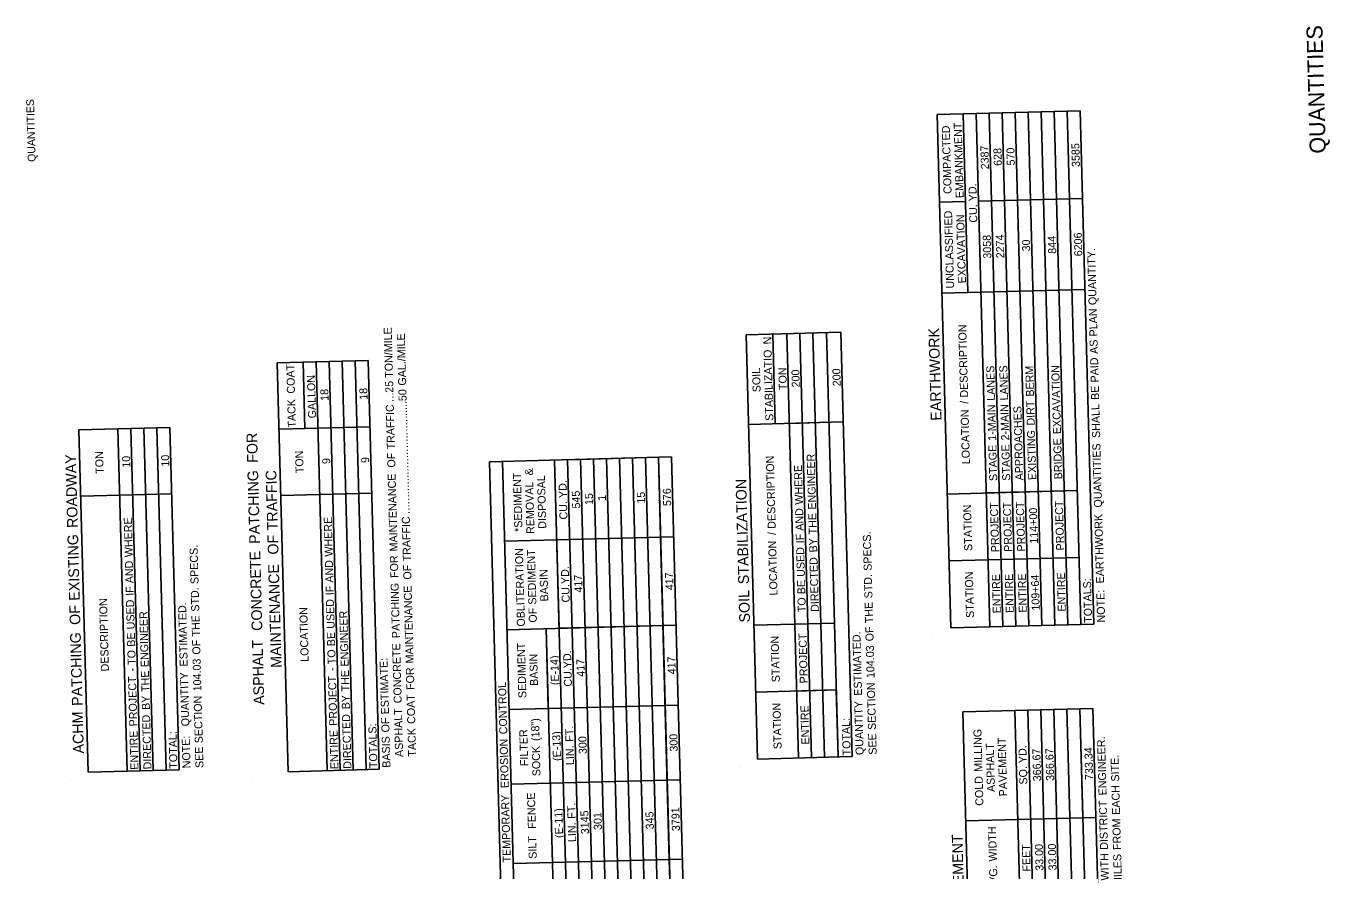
# Model space of a CAD drawing. Extents: x 1930093 to 1931323, y 596452 to 607874.
# Drawn here: x 1930226 to 1931204, y 602346 to 602980 of the extents above; entities that cross this region are included whole.
import ezdxf

# ---------------------------------------------------------------- set-up
doc = ezdxf.new("R2010")
doc.units = 0
for name, color, linetype in [('Default', 7, 'Continuous'), ('R_Border', 7, 'Continuous'), ('R_Border Prem', 7, 'Continuous')]:
    doc.layers.add(name, color=color, linetype=linetype)

msp = doc.modelspace()

# ---------------------------------------------------------------- linework, layer by layer
at = {"layer": 'Default'}
for p, q in [((1931016.35, 602916.08), (1930909.14, 602913.2)), ((1931016.35, 602916.08), (1930909.14, 602913.2)), ((1931026.69, 602531.09), (1931016.35, 602916.08)), ((1930919.48, 602528.21), (1930909.14, 602913.2)), ((1930932.23, 602779.71), (1930928.64, 602913.72)), ((1930948.72, 602529), (1930938.38, 602913.98)), ((1930958.46, 602529.26), (1930948.13, 602914.25)), ((1930968.21, 602529.52), (1930957.87, 602914.51)), ((1930977.96, 602529.78), (1930967.62, 602914.77)), ((1930987.7, 602530.04), (1930977.37, 602915.03)), ((1930997.45, 602530.31), (1930987.11, 602915.29)), ((1931007.2, 602530.57), (1930996.86, 602915.55)), ((1931016.94, 602530.83), (1931006.61, 602915.82)), ((1931016.94, 602530.83), (1931006.61, 602915.82)), ((1930930.4, 602847.93), (1930910.91, 602847.41)), ((1931018.12, 602850.29), (1930940.15, 602848.2)), ((1931019.95, 602782.06), (1930912.74, 602779.18)), ((1931010.2, 602781.8), (1930941.98, 602779.97)), ((1930837.06, 602749.91), (1930765.91, 602748)), ((1930837.06, 602749.91), (1930765.91, 602748)), ((1930845.6, 602431.69), (1930837.06, 602749.91)), ((1930774.45, 602429.78), (1930765.91, 602748)), ((1930787.7, 602681.29), (1930785.89, 602748.54)), ((1930805.16, 602430.61), (1930796.61, 602748.83)), ((1930805.16, 602430.61), (1930796.61, 602748.83)), ((1930814.9, 602430.87), (1930806.36, 602749.09)), ((1930824.65, 602431.13), (1930816.11, 602749.35)), ((1930834.88, 602431.4), (1930826.34, 602749.63)), ((1930482.5, 602728.69), (1930414.27, 602726.86)), ((1930433.77, 602727.38), (1930414.27, 602726.86)), ((1930422.5, 602420.33), (1930414.27, 602726.86)), ((1930435.1, 602677.68), (1930433.77, 602727.38)), ((1930463, 602728.17), (1930443.51, 602727.65)), ((1930451.74, 602421.12), (1930443.51, 602727.65)), ((1930461.49, 602421.38), (1930453.26, 602727.91)), ((1930471.23, 602421.64), (1930463, 602728.17)), ((1930482.5, 602728.69), (1930472.75, 602728.43)), ((1930480.98, 602421.9), (1930472.75, 602728.43)), ((1930490.73, 602422.16), (1930482.5, 602728.69)), ((1930838.87, 602682.66), (1930767.72, 602680.75)), ((1930828.15, 602682.38), (1930798.42, 602681.58)), ((1930333.86, 602678.54), (1930265.64, 602676.71)), ((1930272.53, 602419.89), (1930265.64, 602676.71)), ((1930333.86, 602678.54), (1930294.88, 602677.49)), ((1930301.77, 602420.67), (1930294.88, 602677.49)), ((1930311.52, 602420.94), (1930304.62, 602677.76)), ((1930321.26, 602421.2), (1930314.37, 602678.02)), ((1930331.01, 602421.46), (1930324.12, 602678.28)), ((1930340.76, 602421.72), (1930333.86, 602678.54)), ((1930483.83, 602678.98), (1930415.61, 602677.15)), ((1930483.83, 602678.98), (1930435.1, 602677.68)), ((1930709.99, 602656.45), (1930573.54, 602652.78)), ((1930605.63, 601457.38), (1930573.54, 602652.78)), ((1930606.39, 601792.43), (1930583.29, 602653.05)), ((1930645.38, 601793.48), (1930622.28, 602654.09)), ((1930625.66, 602527.88), (1930622.28, 602654.09)), ((1930700.25, 602656.19), (1930632.02, 602654.35)), ((1930664.11, 601458.95), (1930632.02, 602654.35)), ((1930673.86, 601459.21), (1930641.77, 602654.62)), ((1930683.6, 601459.47), (1930651.52, 602654.88)), ((1930693.35, 601459.73), (1930661.26, 602655.14)), ((1930703.1, 601459.99), (1930671.01, 602655.4)), ((1930712.84, 601460.26), (1930680.75, 602655.66)), ((1930722.59, 601460.52), (1930690.5, 602655.92)), ((1930732.34, 601460.78), (1930700.25, 602656.19)), ((1930701.86, 602596.24), (1930700.25, 602656.19)), ((1930742.08, 601461.04), (1930709.99, 602656.45)), ((1930335.2, 602628.83), (1930266.97, 602627)), ((1930335.2, 602628.83), (1930296.21, 602627.79)), ((1930485.17, 602629.28), (1930416.94, 602627.45)), ((1930485.17, 602629.28), (1930446.18, 602628.23)), ((1931014.25, 602631.22), (1930916.78, 602628.6)), ((1931014.25, 602631.22), (1930946.02, 602629.39)), ((1930711.6, 602596.51), (1930584.9, 602593.11)), ((1930711.6, 602596.51), (1930623.88, 602594.15)), ((1930708.35, 602354.53), (1930701.86, 602596.24)), ((1931015.59, 602581.02), (1930918.13, 602578.41)), ((1931015.59, 602581.02), (1930947.37, 602579.19)), ((1930713.38, 602530.23), (1930586.68, 602526.83)), ((1930622.28, 602290.77), (1930615.92, 602527.61)), ((1930617.53, 602467.67), (1930615.92, 602527.61)), ((1930713.38, 602530.23), (1930625.66, 602527.88)), ((1930832.19, 602531.79), (1930771.76, 602530.17)), ((1930832.19, 602531.79), (1930802.46, 602530.99)), ((1931026.69, 602531.09), (1930919.48, 602528.21)), ((1931026.69, 602531.09), (1930919.48, 602528.21)), ((1930833.54, 602481.6), (1930773.11, 602479.98)), ((1930833.54, 602481.6), (1930803.81, 602480.8)), ((1930834.88, 602431.4), (1930833.54, 602481.6)), ((1930714.99, 602470.29), (1930588.29, 602466.89)), ((1930714.99, 602470.29), (1930627.27, 602467.93)), ((1931025.99, 602467.84), (1930928.53, 602465.22)), ((1931025.99, 602467.84), (1930928.53, 602465.22)), ((1930971.24, 602327.38), (1930967.51, 602466.27)), ((1930987.38, 602089.34), (1930977.26, 602466.53)), ((1930997.13, 602089.6), (1930987, 602466.79)), ((1931006.88, 602089.87), (1930996.75, 602467.05)), ((1931016.62, 602090.13), (1931006.5, 602467.32)), ((1931026.37, 602090.39), (1931016.24, 602467.58)), ((1931018.44, 602385.71), (1931016.24, 602467.58)), ((1931036.12, 602090.65), (1931025.99, 602467.84)), ((1930938.65, 602088.03), (1930928.53, 602465.22)), ((1930845.6, 602431.69), (1930774.45, 602429.78)), ((1930845.6, 602431.69), (1930774.45, 602429.78)), ((1930340.76, 602421.72), (1930272.53, 602419.89)), ((1930340.76, 602421.72), (1930272.53, 602419.89)), ((1930490.73, 602422.16), (1930422.5, 602420.33)), ((1930490.73, 602422.16), (1930422.5, 602420.33)), ((1930716.5, 602414.25), (1930589.79, 602410.85)), ((1930716.5, 602414.25), (1930619.03, 602411.63)), ((1931028.19, 602385.97), (1930930.72, 602383.35)), ((1931018.44, 602385.71), (1930979.46, 602384.66)), ((1930718.09, 602354.79), (1930591.39, 602351.39)), ((1930708.35, 602354.53), (1930630.37, 602352.44)), ((1930712.69, 602192.74), (1930708.35, 602354.53))]:
    msp.add_line(p, q, dxfattribs=at)
at = {"layer": 'R_Border'}
for p, q in [((1930905.99, 602522), (1930905.99, 602522)), ((1930760.97, 602423.57), (1930760.97, 602423.57)), ((1930259.04, 602413.68), (1930259.04, 602413.68)), ((1930395.37, 602413.75), (1930395.37, 602413.75))]:
    msp.add_line(p, q, dxfattribs=at)

# ---------------------------------------------------------------- texts
at = {"layer": 'Default'}
for s, height, p in [('EMBANKMENT', 6, (1930929.13, 602850.62)), ('COMPACTED', 6, (1930920.04, 602853.76)), ('2387', 6, (1930948.06, 602872.19)), ('628', 6, (1930957.74, 602874.78)), ('570', 6, (1930967.49, 602875.06)), ('3585', 6, (1931016.28, 602873.96)), (' YD.', 6, (1930939.01, 602846.01)), ('UNCLASSIFIED', 6, (1930921.95, 602782.79)), ('CU.', 6, (1930939.38, 602832.16)), ('EXCAVATION', 6, (1930930.85, 602786.65)), ('3058', 6, (1930949.86, 602805.18)), ('2274', 6, (1930959.6, 602805.46)), ('30', 6, (1930978.97, 602810.64)), ('844', 6, (1930998.52, 602808.84)), ('6206', 6, (1931018.08, 602806.98)), (' QUANTITY.', 6, (1931028.88, 602768.15)), (' PLAN', 6, (1931029.51, 602744.62)), (' TON/MILE', 6, (1930501.21, 602713.6)), ('EARTHWORK', 8, (1930912.48, 602683.7)), (' DESCRIPTION', 6, (1930932.53, 602698.78)), (' GAL./MILE', 6, (1930511.12, 602707.73)), ('N', 6, (1930784.9, 602740.89)), (' AS', 6, (1931029.86, 602731.55)), ('STABILIZATIO', 6, (1930786.44, 602683.49)), (' PAID', 6, (1931030.44, 602710.11)), (' COAT', 6, (1930427.7, 602701.73)), ('SOIL', 6, (1930776.86, 602704.99)), ('TON', 6, (1930796.55, 602706.66)), ('200', 6, (1930806.25, 602708.65)), ('200', 6, (1930836.95, 602709.47)), (' LANES', 6, (1930952.78, 602696.39)), (' LANES', 6, (1930962.52, 602696.65)), (' BERM', 6, (1930981.95, 602699.48)), (' EXCAVATION', 6, (1931002.21, 602671.38)), ('GALLON', 6, (1930443.45, 602685.4)), ('25', 6, (1930501.45, 602704.61)), ('18', 6, (1930452.85, 602698.55)), ('18', 6, (1930482.09, 602699.33)), ('…', 6, (1930501.65, 602697.22)), ('.....50', 6, (1930511.67, 602687.18)), (' BE', 6, (1931030.79, 602697.05)), ('TACK', 6, (1930428.33, 602678.47)), (' TRAFFIC', 6, (1930502.65, 602659.84)), (' /', 6, (1930932.65, 602694.11)), ('LOCATION', 6, (1930933.81, 602651.02)), (' 1-MAIN', 6, (1930953.58, 602666.35)), (' 2-MAIN', 6, (1930963.33, 602666.61)), ('APPROACHES', 6, (1930973.83, 602638.91)), (' DIRT', 6, (1930982.54, 602677.77)), (' SHALL', 6, (1931031.55, 602668.47)), ('…', 6, (1930511.87, 602679.78)), (' FOR', 8, (1930399.88, 602649.13)), ('…', 6, (1930512.07, 602672.38)), ('…', 6, (1930512.27, 602664.99)), ('EXISTING', 6, (1930983.57, 602639.17)), ('…', 6, (1930512.47, 602657.59)), ('STAGE', 6, (1930954.33, 602638.39)), ('STAGE', 6, (1930964.08, 602638.65)), ('BRIDGE', 6, (1931003.07, 602639.7)), (' QUANTITIES', 6, (1931032.95, 602616.29)), (' ROADWAY', 8, (1930264.86, 602600.27)), ('TON', 6, (1930284.15, 602643.82)), ('10', 6, (1930304.21, 602648.41)), ('10', 6, (1930333.45, 602649.2)), ('TON', 6, (1930434.12, 602644.26)), ('9', 6, (1930454.12, 602651.17)), ('9', 6, (1930483.36, 602651.96)), (' OF', 6, (1930503.02, 602646.26)), ('…', 6, (1930512.66, 602650.19)), (' DESCRIPTION', 6, (1930788.24, 602600.37)), (' ENGINEER', 6, (1930818.52, 602614.74)), (' PATCHING', 8, (1930401.51, 602588.34)), (' TRAFFIC', 8, (1930414.89, 602598.42)), (' MAINTENANCE', 6, (1930504.71, 602583.38)), ('…', 6, (1930512.86, 602642.8)), ('…', 6, (1930513.06, 602635.4)), ('*SEDIMENT', 6, (1930598.21, 602600.24)), (' &', 6, (1930606.14, 602640.39)), ('DISPOSAL', 6, (1930616.15, 602602.62)), (' WHERE', 6, (1930808.67, 602618.45)), ('…', 6, (1930513.26, 602628)), ('REMOVAL', 6, (1930607.26, 602598.73)), (' YD.', 6, (1930631.65, 602623.42)), ('576', 6, (1930709.78, 602619.61)), (' STABILIZATION', 8, (1930768.18, 602558.06)), ('…', 6, (1930513.46, 602620.61)), ('545', 6, (1930641.56, 602617.79)), ('15', 6, (1930651.24, 602620.38)), ('1', 6, (1930660.91, 602623.58)), ('15', 6, (1930690.23, 602621.43)), ('PROJECT', 6, (1931004.5, 602586.35)), ('…', 6, (1930513.66, 602613.21)), ('CU.', 6, (1930632.02, 602609.56)), (' AND', 6, (1930809.19, 602598.88)), (' THE', 6, (1930819.02, 602596.09)), ('STATION', 6, (1930935.56, 602585.92)), ('PROJECT', 6, (1930955.76, 602585.04)), ('PROJECT', 6, (1930965.51, 602585.31)), ('PROJECT', 6, (1930975.26, 602585.57)), ('114+00', 6, (1930984.85, 602591.41)), ('  EARTHWORK', 6, (1931034.54, 602557.17)), (' WHERE', 6, (1930306.07, 602579.08)), (' WHERE', 6, (1930456.04, 602579.52)), (' TRAFFIC', 6, (1930514.66, 602575.83)), (' EXISTING', 8, (1930266.33, 602545.69)), (' OF', 8, (1930415.38, 602580.31)), (' /', 6, (1930788.36, 602595.7)), (' IF', 6, (1930809.44, 602589.49)), (' BY', 6, (1930819.38, 602582.65)), (' SPECS.', 6, (1930860.23, 602568.85)), (' SPECS.', 6, (1930355.38, 602558.88)), (' CONCRETE', 8, (1930403.26, 602523.09)), ('OBLITERATION', 6, (1930600.12, 602529.24)), (' SEDIMENT', 6, (1930608.74, 602543.47)), ('LOCATION', 6, (1930789.52, 602552.61)), (' USED', 6, (1930810.12, 602564.32)), (' AND', 6, (1930306.6, 602559.5)), ('MAINTENANCE', 8, (1930417.58, 602498.3)), (' AND', 6, (1930456.57, 602559.95)), (' FOR', 6, (1930505.24, 602563.47)), (' OF', 6, (1930515.03, 602562.25)), ('DIRECTED', 6, (1930820.52, 602540.26)), ('BASIN', 6, (1930617.62, 602548.11)), ('CU.YD.', 6, (1930633.69, 602547.33)), ('417', 6, (1930643.25, 602554.71)), ('417', 6, (1930711.48, 602556.53)), (' STD.', 6, (1930860.78, 602548.17)), ('STATION', 6, (1930936.91, 602535.73)), ('ENTIRE', 6, (1930957, 602539.18)), ('ENTIRE', 6, (1930966.74, 602539.44)), ('ENTIRE', 6, (1930976.49, 602539.7)), ('109+64', 6, (1930986.2, 602541.22)), ('ENTIRE', 6, (1931005.73, 602540.49)), ('TOTALS:', 6, (1931025.46, 602532.03)), (' IF', 6, (1930306.85, 602550.11)), (' STD.', 6, (1930355.94, 602538.2)), (' IF', 6, (1930456.82, 602550.56)), (' PATCHING', 6, (1930506.45, 602518.36)), (' MAINTENANCE', 6, (1930516.71, 602499.37)), ('SOIL', 8, (1930768.88, 602532.32)), (' BE', 6, (1930810.47, 602551.26)), ('NOTE:', 6, (1931035.21, 602532.29)), (' OF', 8, (1930266.81, 602527.58)), ('DESCRIPTION', 6, (1930288.13, 602495.62)), (' USED', 6, (1930307.53, 602524.95)), (' ESTIMATED.', 6, (1930347.29, 602497.09)), (' USED', 6, (1930457.49, 602525.39)), ('TO', 6, (1930810.77, 602540)), (' THE', 6, (1930861.28, 602529.52)), (' ENGINEER', 6, (1930318.04, 602496.62)), (' THE', 6, (1930356.44, 602519.55)), ('LOCATION', 6, (1930437.92, 602502.82)), (' ENGINEER', 6, (1930468.01, 602497.06)), ('OF', 6, (1930609.04, 602532.22)), (' BE', 6, (1930457.84, 602512.33)), (' OF', 6, (1930861.65, 602515.94)), (' PATCHING', 8, (1930268.45, 602466.8)), (' BE', 6, (1930307.88, 602511.89)), (' OF', 6, (1930356.8, 602505.97)), ('ASPHALT', 8, (1930404.67, 602470.55)), (' CONCRETE', 6, (1930507.76, 602469.45)), ('SEDIMENT', 6, (1930601.18, 602475.64)), ('STATION', 6, (1930791.27, 602487.51)), ('PROJECT', 6, (1930812.2, 602486.65)), (' ESTIMATED.', 6, (1930852.99, 602475.2)), (' TO', 6, (1930308.24, 602498.3)), (' TO', 6, (1930458.21, 602498.74)), ('BASIN', 6, (1930609.94, 602484.75)), ('(E-14)', 6, (1930625.61, 602485.29)), ('CU.YD.', 6, (1930635.39, 602484.22)), ('417', 6, (1930713.17, 602493.43)), (' 104.03', 6, (1930862.39, 602488.38)), (' -', 6, (1930308.37, 602493.44)), (' THE', 6, (1930318.54, 602477.98)), (' 104.03', 6, (1930357.54, 602478.41)), (' -', 6, (1930458.34, 602493.88)), (' THE', 6, (1930468.51, 602478.42)), (' ESTIMATE:', 6, (1930498.23, 602461.2)), (' FOR', 6, (1930517.25, 602479.47)), ('417', 6, (1930644.94, 602491.6)), (' PROJECT', 6, (1930309.48, 602452.17)), ('   QUANTITY', 6, (1930348.61, 602447.8)), (' PROJECT', 6, (1930459.45, 602452.61)), (' CONTROL', 6, (1930586.97, 602446.19)), (' SECTION', 6, (1930863.43, 602449.48)), (' BY', 6, (1930318.9, 602464.53)), (' SECTION', 6, (1930358.59, 602439.51)), (' BY', 6, (1930468.87, 602464.98)), (' COAT', 6, (1930517.93, 602454.03)), ('ASPHALT', 6, (1930508.78, 602431.43)), ('STATION', 6, (1930792.62, 602437.32)), ('ENTIRE', 6, (1930813.44, 602440.79)), ('QUANTITY', 6, (1930854.12, 602432.9)), ('ACHM', 8, (1930269.32, 602434.08)), ('DIRECTED', 6, (1930320.04, 602422.14)), ('DIRECTED', 6, (1930470.01, 602422.58)), (' OF', 6, (1930498.6, 602447.62)), (' (18")', 6, (1930611.11, 602441.18)), ('TOTAL:', 6, (1930844.38, 602432.63)), ('ENTIRE', 6, (1930310.29, 602421.88)), ('TOTAL:', 6, (1930339.53, 602422.66)), ('NOTE:', 6, (1930349.28, 602422.93)), ('ENTIRE', 6, (1930460.26, 602422.32)), ('TOTALS:', 6, (1930489.5, 602423.11)), ('TACK', 6, (1930518.53, 602431.69)), ('FILTER', 6, (1930602.55, 602424.57)), ('(E-13)', 6, (1930627.13, 602428.46)), (' FT.', 6, (1930636.56, 602440.61)), ('300', 6, (1930714.73, 602435.45)), ('SEE', 6, (1930863.87, 602433.16)), (' MILLING', 6, (1930943.29, 602418.18)), ('SEE', 6, (1930359.02, 602423.19)), ('BASIS', 6, (1930499.25, 602423.37)), (' EROSION', 6, (1930588.05, 602405.88)), ('SOCK', 6, (1930611.76, 602416.98)), ('LIN.', 6, (1930636.97, 602425.36)), ('300', 6, (1930646.5, 602433.62)), ('ASPHALT', 6, (1930952.64, 602405.19)), ('PAVEMENT', 6, (1930961.74, 602401.93)), (' YD.', 6, (1930976.51, 602424.62)), ('366.67', 6, (1930987.24, 602413.21)), ('366.67', 6, (1930996.99, 602413.47)), ('733.34', 6, (1931026.23, 602414.16)), (' ENGINEER.', 6, (1931036.35, 602400.4)), (' SITE.', 6, (1931045.83, 602410.76)), ('SQ.', 6, (1930976.88, 602410.75)), ('COLD', 6, (1930943.92, 602394.85)), (' EACH', 6, (1931046.5, 602385.82)), ('TEMPORARY', 6, (1930589.49, 602352.32)), ('  FENCE', 6, (1930608.44, 602373.1)), (' DISTRICT', 6, (1931037.45, 602359.6)), ('(E-11)', 6, (1930628.68, 602370.71)), (' FT.', 6, (1930638.11, 602382.86)), ('3145', 6, (1930648.11, 602373.51)), ('301', 6, (1930657.78, 602376.7)), ('345', 6, (1930696.78, 602377.14)), ('3791', 6, (1930716.33, 602375.85)), ('LIN.', 6, (1930638.52, 602367.61)), (' WIDTH', 6, (1930954.1, 602350.83)), (' FROM', 6, (1931047.21, 602359.45)), ('SILT', 6, (1930608.92, 602355.11)), (' PAVEMENT', 8, (1930929.82, 602311.62)), ('FEET', 6, (1930979.31, 602345.5)), ('33.00', 6, (1930989.04, 602346.1)), ('33.00', 6, (1930998.79, 602346.36)), ('AVG.', 6, (1930954.64, 602330.92)), (' WITH', 6, (1931038.07, 602336.54)), (' MILES', 6, (1931047.93, 602332.41))]:
    msp.add_text(s, height=height, rotation=91.53769, dxfattribs=at).set_placement(p)
at = {"layer": 'R_Border'}
msp.add_text('QUANTITIES', height=12, rotation=91.53769, dxfattribs=at).set_placement((1931200.69, 602884.08))
at = {"layer": 'R_Border Prem'}
msp.add_text('QUANTITIES', height=5.862, rotation=91.53769, dxfattribs=at).set_placement((1930233.13, 602877.83))

doc.saveas('drawing.dxf')
